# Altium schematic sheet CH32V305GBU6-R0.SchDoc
size 304 x 228 mm; SheetNumber: 0; SheetTotal: 0
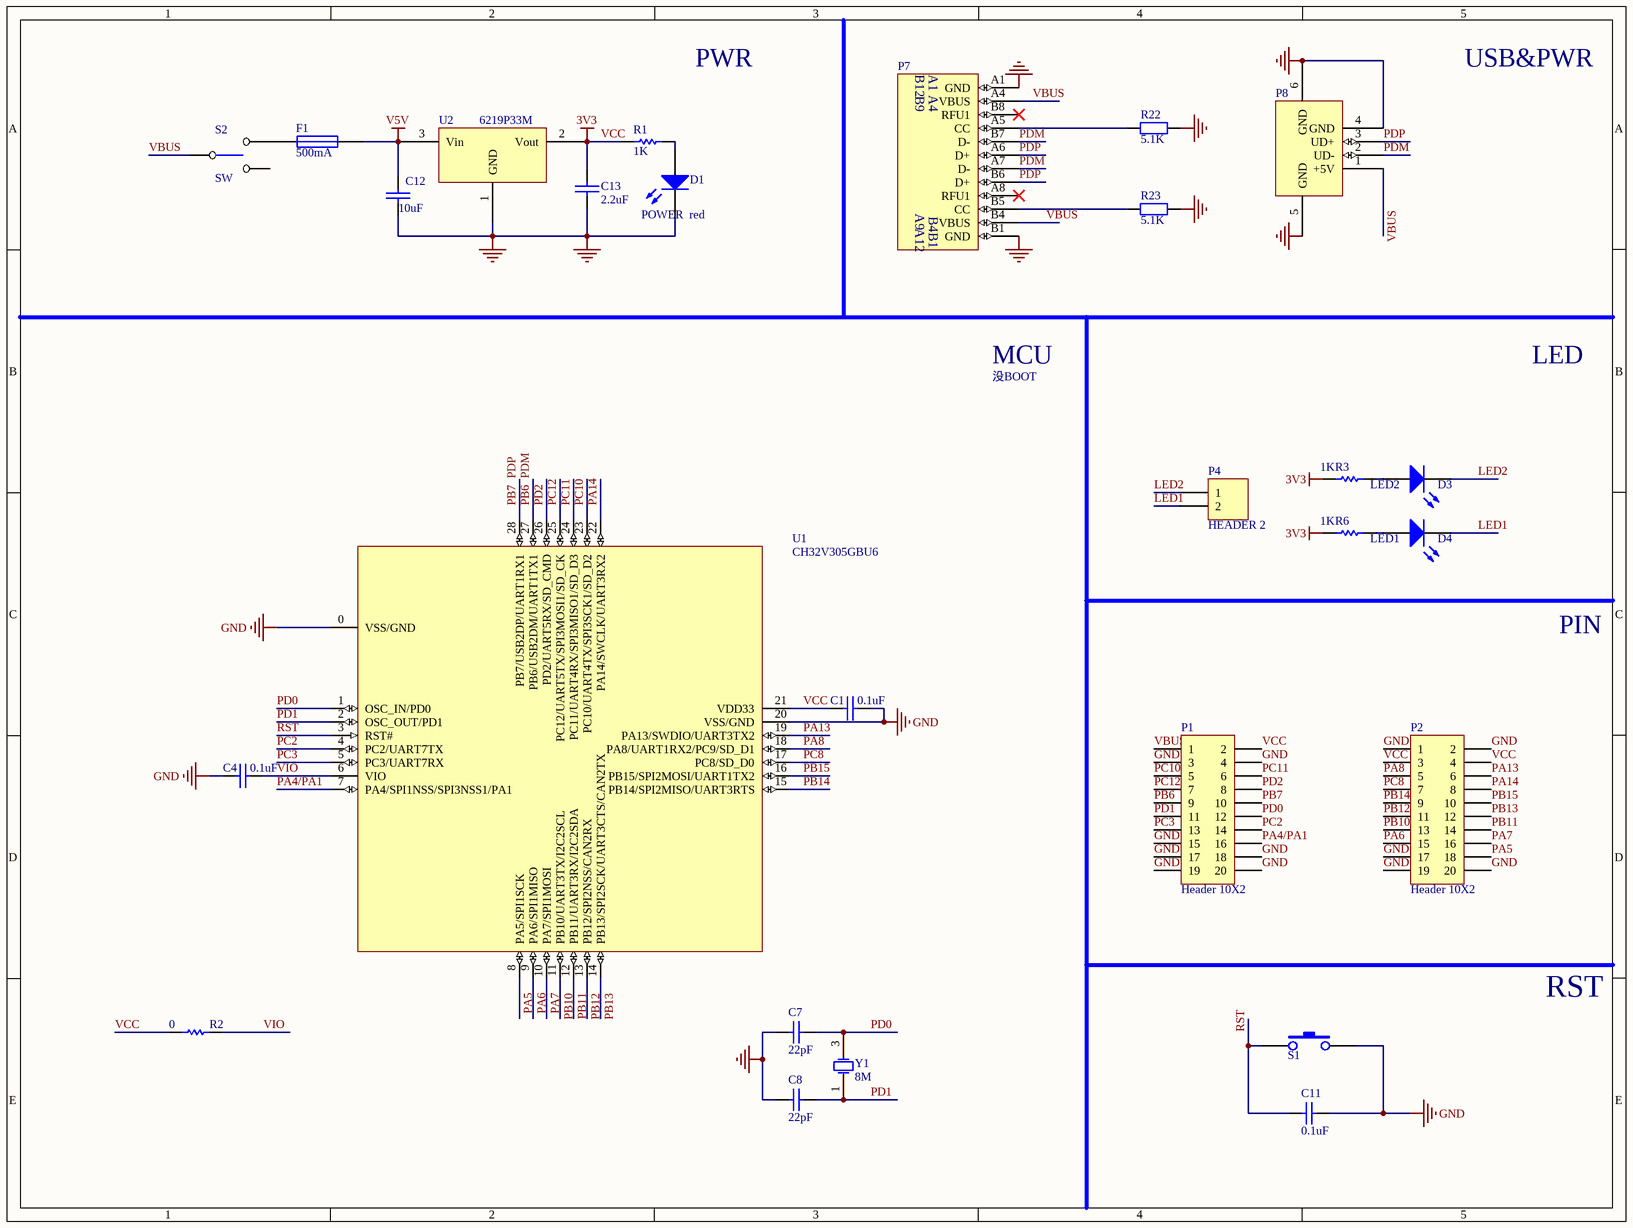
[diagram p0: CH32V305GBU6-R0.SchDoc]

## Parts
C1  0.1uF  [0603_C]
C4  0.1uF  [0603_C]
C7  22pF  [0603_C]
C8  22pF  [0603_C]
C11  0.1uF  [0603_C]
C12  10uF  [0603_C]
C13  2.2uF  [0603_C]
D1  POWER  red  [0603+]
D3  LED2  [0603+]
D4  LED1  [0603+]
F1  500mA  [0603]
P1  Header 10X2  [IDC20-2.54mm]
P2  Header 10X2  [IDC20-2.54mm]
P4  HEADER 2  [SIP2-2.54mm]
P7  TYPE-C  [TYPE-C-Receptacle-2.0]  (value not drawn)
P8  USB_A  [USBAF]  (value not drawn)
R1  1K  [0603]
R2  0  [0603]
R3  1K  [0603]
R6  1K  [0603]
R22  5.1K  [0603]
R23  5.1K  [0603]
S1  RST  [SMD_6.1x3.65x2.5mm-KEY]  (value not drawn)
S2  SW  [SW1]
U1  CH32V305GBU6  [QFN28_4X4]
U2  6219P33M  [SOT-23]
Y1  8M  [XT3225]

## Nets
GND: C1.2 C4.2 C7.1 C8.1 C11.1 C12.2 C13.2 D1.2(K) P1.3 P1.4 P1.15 P1.17 P1.18 P1.19 P1.20 P2.1 P2.2 P2.17 P2.19 P2.20 P7.A1(GND) P7.B1(GND) P8.4(GND) P8.5(GND) P8.6(GND) R22.2 R23.2 S1.2 U1.0(VSS/GND) U1.20(VSS/GND) U2.1(GND)
V5V: C12.1 F1.2 U2.3(Vin)
VCC: C1.1 C13.1 P1.2 P2.3 P2.4 R1.2 R2.1 R3.1 R6.1 U1.21(VDD33) U2.2(Vout)  [also labelled 3V3]
LED1: D4.2(K) P4.2
LED2: D3.2(K) P4.1
PA4/PA1: P1.16 U1.7(PA4/SPI1NSS/SPI3NSS1/PA1)
PA5: P2.18 U1.8(PA5/SPI1SCK)
PA6: P2.15 U1.9(PA6/SPI1MISO)
PA7: P2.16 U1.10(PA7/SPI1MOSI)
PA8: P2.5 U1.18(PA8/UART1RX2/PC9/SD_D1)
PA13: P2.6 U1.19(PA13/SWDIO/UART3TX2)
PA14: P2.8 U1.22(PA14/SWCLK/UART3RX2)
PB6: P1.9 P7.A7(D-) P7.B7(D-) P8.2(UD-) U1.27(PB6/USB2DM/UART1TX1)  [also labelled PDM]
PB7: P1.10 P7.A6(D+) P7.B6(D+) P8.3(UD+) U1.28(PB7/USB2DP/UART1RX1)  [also labelled PDP]
PB10: P2.13 U1.11(PB10/UART3TX/I2C2SCL)
PB11: P2.14 U1.12(PB11/UART3RX/I2C2SDA)
PB12: P2.11 U1.13(PB12/SPI2NSS/CAN2RX)
PB13: P2.12 U1.14(PB13/SPI2SCK/UART3CTS/CAN2TX)
PB14: P2.9 U1.15(PB14/SPI2MISO/UART3RTS)
PB15: P2.10 U1.16(PB15/SPI2MOSI/UART1TX2)
PC2: P1.14 U1.4(PC2/UART7TX)
PC3: P1.13 U1.5(PC3/UART7RX)
PC8: P2.7 U1.17(PC8/SD_D0)
PC10: P1.5 U1.23(PC10/UART4TX/SPI3SCK1/SD_D2)
PC11: P1.6 U1.24(PC11/UART4RX/SPI3MISO1/SD_D3)
PC12: P1.7 U1.25(PC12/UART5TX/SPI3MOSI1/SD_CK)
PD0: C7.2 P1.12 U1.1(OSC_IN/PD0) Y1.3(OSC2)
PD1: C8.2 P1.11 U1.2(OSC_OUT/PD1) Y1.1(OSC1)
PD2: P1.8 U1.26(PD2/UART5RX/SD_CMD)
RST: C11.2 S1.1 U1.3(RST#)
VBUS: P1.1 P7.A4(VBUS) P7.B4(VBUS) P8.1(+5V) S2.1
VIO: C4.1 R2.2 U1.6(VIO)
NetD1_1: D1.1(A) R1.1
NetD3_1: D3.1(A) R3.2
NetD4_1: D4.1(A) R6.2
NetF1_1: F1.1 S2.3
NetP7_A5: P7.A5(CC) R22.1
NetP7_B5: P7.B5(CC) R23.1

Not connected (* = marked no-connect by the designer): P7 A8(RFU1)* B8(RFU1)*; S2 2

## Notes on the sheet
- PWR
- USB&PWR
- MCU
- LED
- 没BOOT
- PIN
- RST

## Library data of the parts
C1 C4 C12 C13 = CAP: Capacitor
C7 C8 C11 = Cap: Capacitor
D1 D3 D4 = LED0: Typical INFRARED GaAs LED
F1 = FUSE1: Fuse
P1 P2 = Header 10X2: Header, 10-Pin, Dual row
P4 = HEADER 2: Header, 2-Pin
P7 = TYPE-C1
P8 = USB: USB Port
R1-R3 R6 = Res Semi: Semiconductor Resistor
R22 R23 = Res2: Resistor
S1 = KEY
U1 = CH32V305GBU6: RISC-V MCU, 144MHz, USB_480M, CAN, UART*4, SPI*3, SDIO
Y1 = XTAL: Crystal Oscillator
